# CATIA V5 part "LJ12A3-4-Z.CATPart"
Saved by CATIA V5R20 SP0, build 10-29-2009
Part number: LJ12A3-4-Z
Bounding box of the stored display mesh (mm): x -6 to 6, y -40 to 27, z -5.999 to 5.999
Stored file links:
  C:\Users\Andi\Desktop\Plasma\LJ12A3-4-Z.CATPart
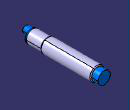
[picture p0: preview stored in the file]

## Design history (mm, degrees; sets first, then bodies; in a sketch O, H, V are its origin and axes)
Body1 (main body)
  Sketch1 on yz-plane, origin (0, 0, 0), H (0, 1, 0), V (0, 0, 1)
    point P1 (-21.5, 0)
    line L1 (-21.5, 0) -> (21.5, 0)
    line L2 (21.5, 0) -> (21.5, 6)
    line L3 (21.5, 6) -> (-21.5, 6)
    line L4 (-21.5, 6) -> (-21.5, 0)
    length L3 = 43
    length L2 = 6
    coincidence: P1 H
    horizontal: L1 H, L3 H
    vertical: L2 V, L4 V
    symmetry: L2 L4 V
  Shaft1: profile Sketch1, axis Sketch1.L1, angle 360
  Sketch2 on face of Shaft1 from Sketch1.L2, origin (0, 21.5, 0), H (-1, 0, 0), V (0, 0, 1)
    circle A1 centre (0, 0) radius 5.25
    radius A1 = 5.25
  Pad1: profile Sketch2, direction (0, 1, 0), length 5.5
  Chamfer1: length 0.75, angle 45, on edge [face of Shaft1 from Sketch1.L3 | face of Shaft1 from Sketch1.L2]; edge [face of Shaft1 from Sketch1.L4 | face of Shaft1 from Sketch1.L3]
  Sketch3 on face of Shaft1 from Sketch1.L4, origin (0, -21.5, 0), H (1, 0, 0), V (0, 0, 1)
    circle A1 centre (0, 0) radius 5.5
    radius A1 = 5.5
  Pad2: profile Sketch3, direction (0, -1, 0), length 12.5
  Sketch4 on end face of Pad2, origin (0, -34, 0), H (1, 0, 0), V (0, 0, 1)
    circle A1 centre (0, 0) radius 5.45
    radius A1 = 5.45
  Pad3: profile Sketch4, direction (0, -1, 0), length 1
  Sketch5 on end face of Pad3, origin (0, -35, 0), H (1, 0, 0), V (0, 0, 1)
    circle A1 centre (0, 2.45) radius 3
    point P1 (0, 2.45)
    radius A1 = 3
    distance P1 H = 2.45
    coincidence: P1 V
  Pad4: profile Sketch5, direction (0, -1, 0), length 5
  Chamfer2: length 5, angle 3, on edge [face of Pad4 from Sketch5.A1 | end face of Pad4]
  Sketch6 on end face of Pad3, origin (0, -35, 0), H (1, 0, 0), V (0, 0, 1)
    circle A1 centre (0, -3) radius 1.5
    point P1 (0, -3)
    radius A1 = 1.5
    distance P1 H = 3
    coincidence: V P1
  Pad5: profile Sketch6, direction (0, -1, 0), length 1
  Fillet1: radius 1, on edge [face of Pad5 from Sketch6.A1 | end face of Pad5]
